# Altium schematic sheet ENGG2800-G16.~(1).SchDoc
size A3
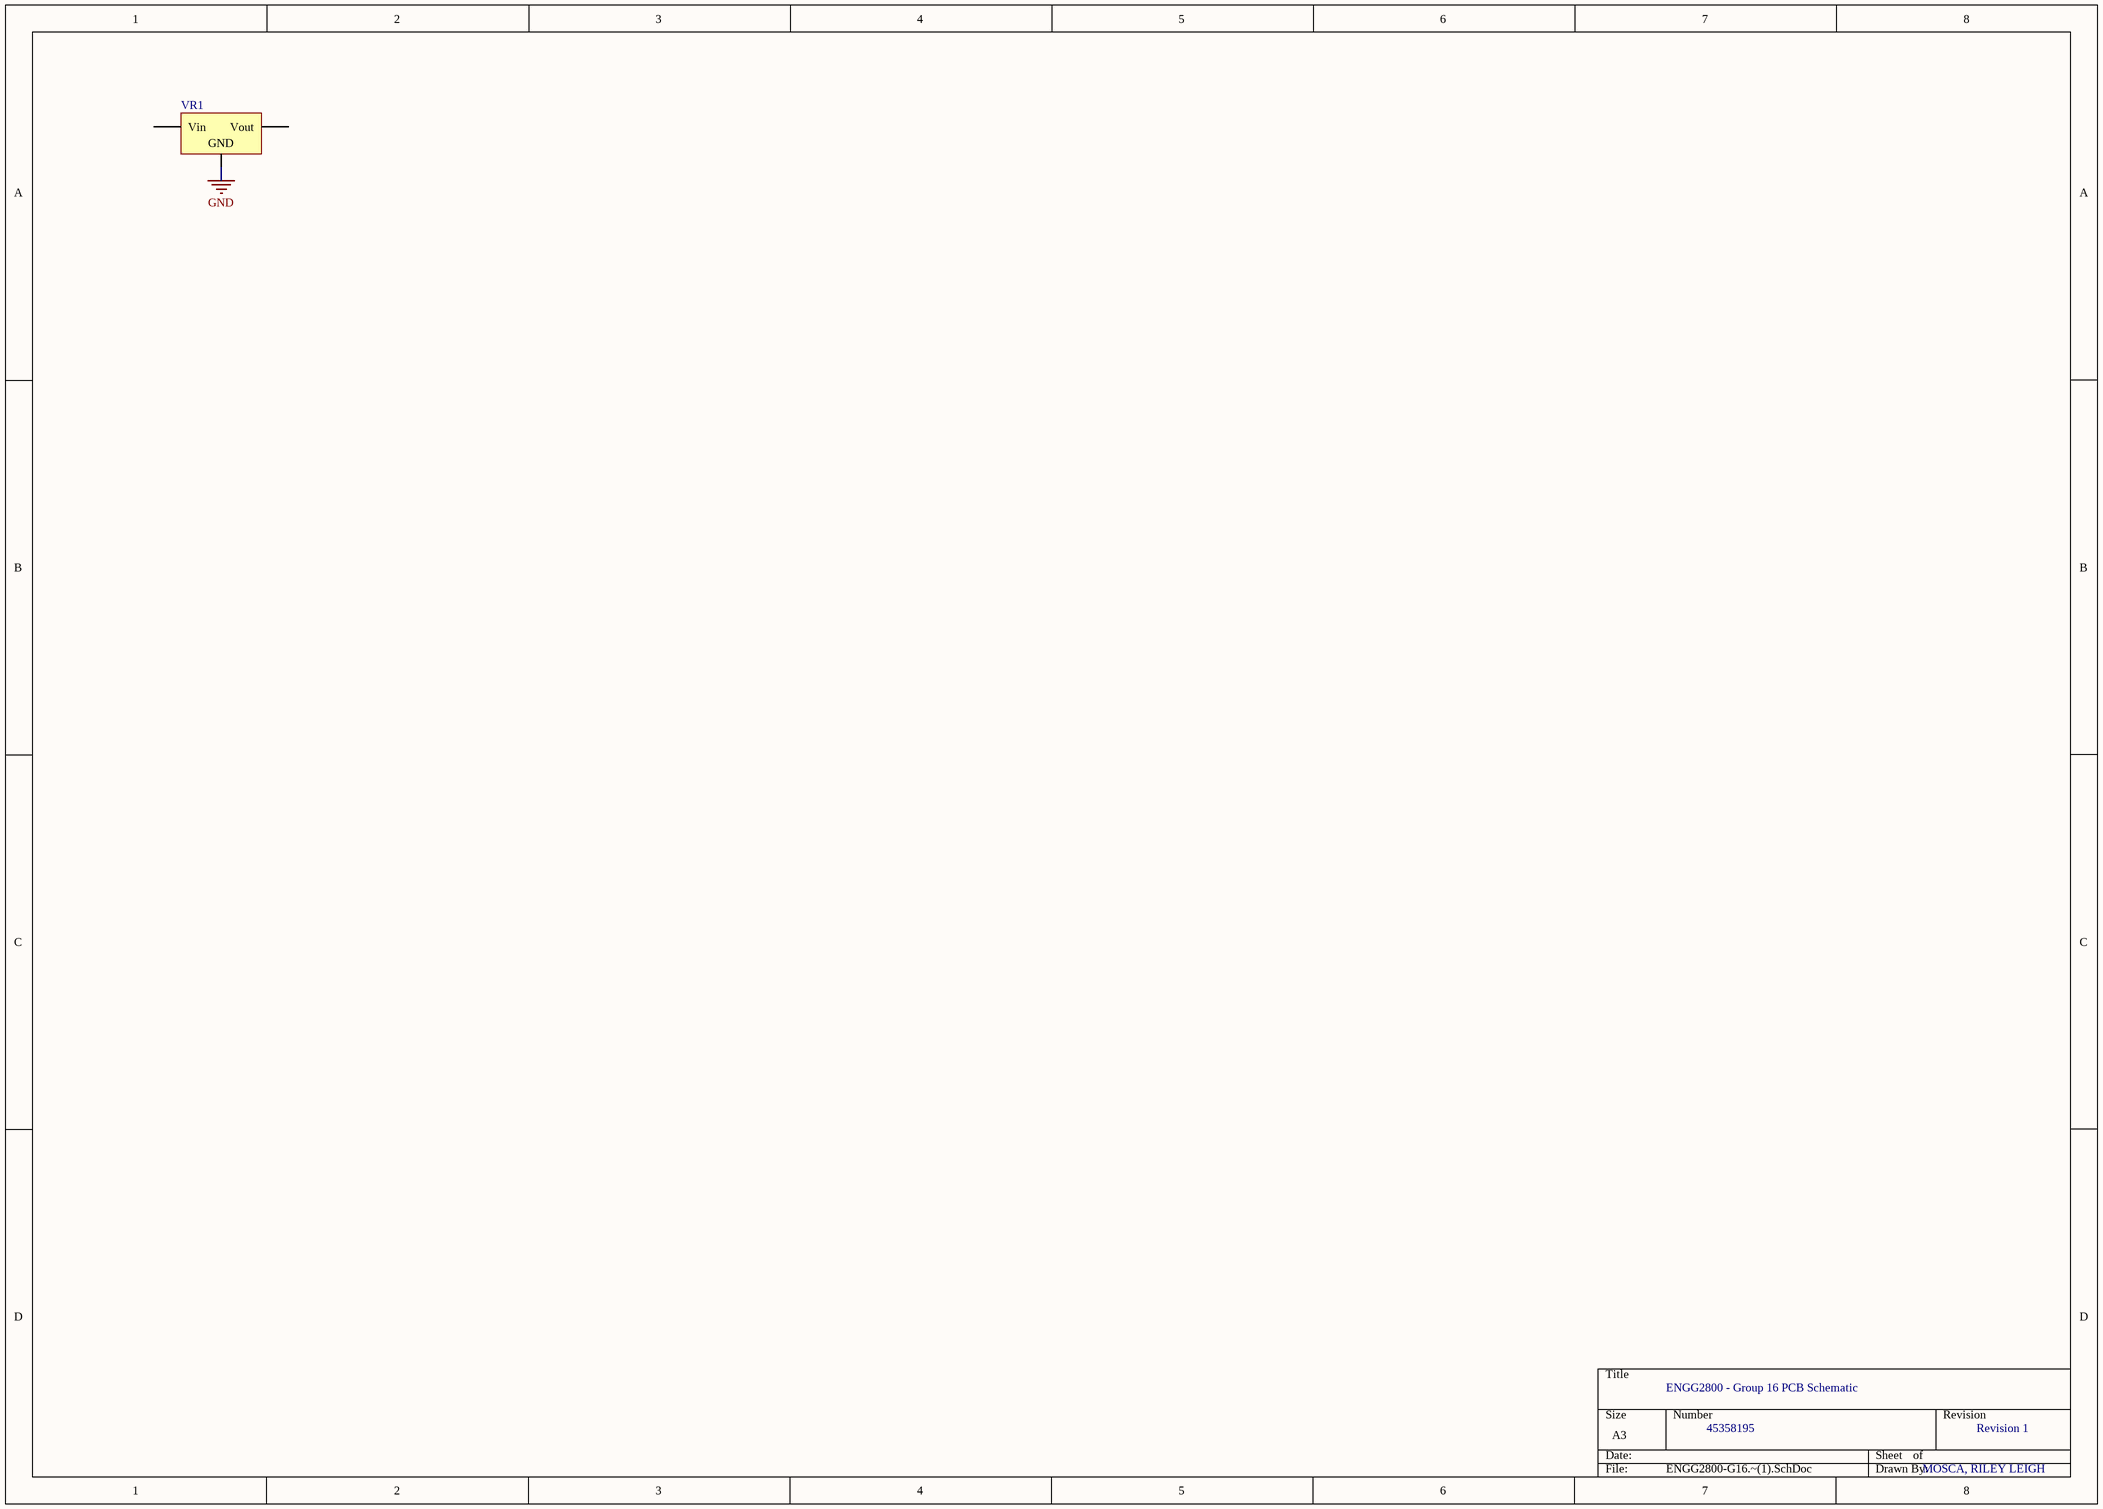
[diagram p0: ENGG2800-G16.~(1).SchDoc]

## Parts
VR1  Volt Reg  [D2PAK_N]  (value not drawn)

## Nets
GND: VR1.2(GND)

Not connected (* = marked no-connect by the designer): VR1 1(Vin) 3(Vout)

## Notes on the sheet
- ENGG2800 - Group 16 PCB Schematic
- 45358195
- Revision 1
- MOSCA, RILEY LEIGH

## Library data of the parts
VR1 = Volt Reg: Voltage Regulator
